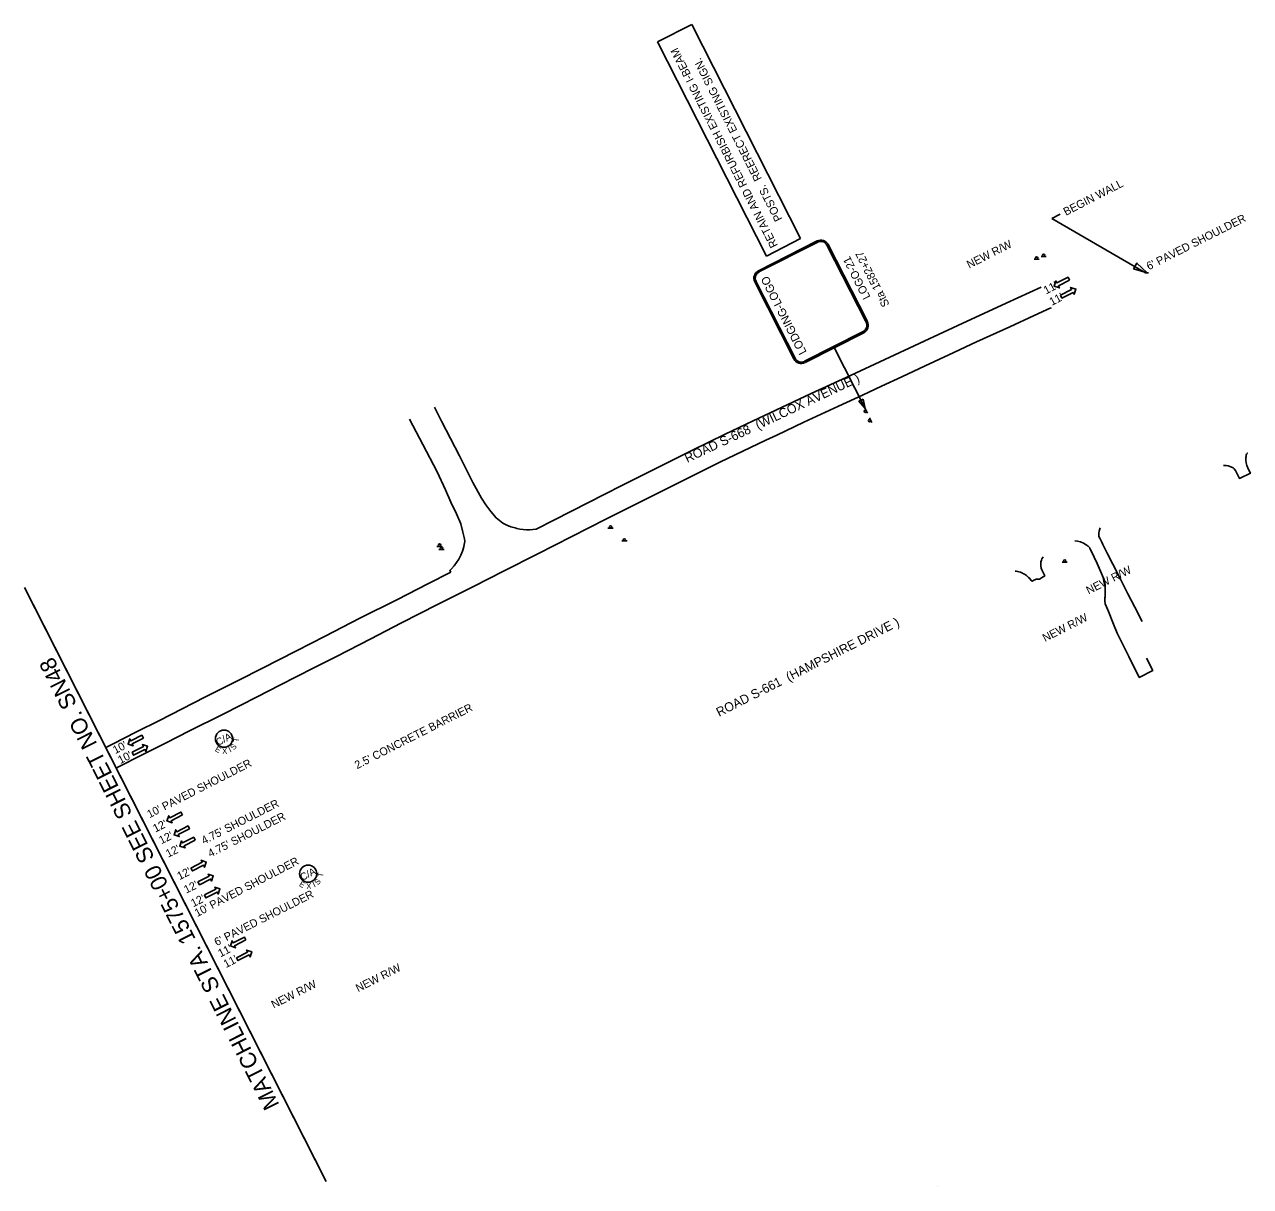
# Model space of a CAD drawing. Extents: x 1804682 to 1806347, y 1188229 to 1189604.
# Drawn here: x 1804682 to 1805754, y 1188229 to 1189245 of the extents above; entities that cross this region are included whole.
import ezdxf

# ---------------------------------------------------------------- set-up
doc = ezdxf.new("R2010")
doc.units = 0
for name, color, linetype in [('RD_EX_Road', 7, 'Continuous'), ('RD_PD_Final_LnLine', 7, 'Continuous'), ('RD_PD_Final_TX', 7, 'Continuous'), ('RD_PD_RW_TX', 7, 'Continuous'), ('RD_PD_WallFill', 7, 'Continuous'), ('RD_SHT_MatchLine', 7, 'Continuous'), ('RD_SHT_ShtClip', 7, 'Continuous'), ('RD_SHT_TX', 7, 'Continuous'), ('RD_Sketch8', 7, 'Continuous'), ('RD_TX_RoadID', 7, 'Continuous'), ('SN_P_Signs', 7, 'Continuous'), ('TERMINATOR', 7, 'Continuous')]:
    doc.layers.add(name, color=color, linetype=linetype)

# ---------------------------------------------------------------- blocks, each defined once
blk = doc.blocks.new('SARRW2')
at = {"layer": 'RD_PD_Final_LnLine'}
blk.add_lwpolyline([(-12, 1.2), (-12, -1.2), (-2.83, -1.2), (-2.83, -2.83), (0, 0), (-2.83, 2.83), (-2.83, 1.2)], close=True, dxfattribs=at)

msp = doc.modelspace()

# ---------------------------------------------------------------- linework, layer by layer
at = {"layer": 'RD_EX_Road'}
for points in [[(1805571.1, 1189015.4), (1805540.6, 1189001.4), (1805498.2, 1188981.7), (1805468.8, 1188968), (1805434.5, 1188952), (1805404.4, 1188938.1), (1805369.9, 1188922.2), (1805339.2, 1188907.8), (1805319.2, 1188898.3), (1805294.8, 1188886.7), (1805266.3, 1188872.8), (1805235.3, 1188857.4), (1805204.4, 1188841.9), (1805174.6, 1188826.7), (1805145.5, 1188811.9), (1805129.4, 1188803.7)], [(1804762.1, 1188594.8), (1804764.7, 1188596.2), (1804784.2, 1188606.1), (1804805.7, 1188616.9), (1804825.6, 1188627), (1804855.5, 1188642), (1804885.3, 1188657.2), (1804905.2, 1188667.2), (1804934.9, 1188682.4), (1804954.7, 1188692.5), (1804984.8, 1188707.9), (1805011, 1188721.4), (1805043.7, 1188738.1), (1805074.6, 1188753.7), (1805100.9, 1188766.9), (1805131, 1188782.2), (1805190.5, 1188812.4), (1805241, 1188837.9), (1805290.2, 1188862.3), (1805330.3, 1188881.5), (1805340, 1188886), (1805363.6, 1188897.2), (1805393.8, 1188911.2), (1805414.8, 1188920.9), (1805431.4, 1188928.6), (1805449.3, 1188937), (1805469.6, 1188946.4), (1805490.5, 1188956.1), (1805514.7, 1188967.5), (1805543.6, 1188980.7), (1805565.1, 1188990.5), (1805579.6, 1188997.1)], [(1805129.4, 1188803.7), (1805126.5, 1188803.3), (1805123.7, 1188803.1), (1805120.9, 1188803.2), (1805118, 1188803.4), (1805115.2, 1188803.8), (1805112.4, 1188804.4), (1805111.1, 1188804.8), (1805107.4, 1188805.9), (1805103.8, 1188807.3), (1805100.4, 1188809.1), (1805097.3, 1188811.2), (1805094.4, 1188813.6), (1805089.8, 1188819.2), (1805085.4, 1188825.1), (1805081.7, 1188830.7), (1805074.1, 1188844.5), (1805062.3, 1188867.7), (1805046.7, 1188898.2), (1805040.5, 1188910.4)], [(1805018.7, 1188899.9), (1805030.2, 1188877.8), (1805042.8, 1188853.9), (1805050.1, 1188838.2), (1805054.9, 1188827.4), (1805059.6, 1188817.1), (1805063.4, 1188808.3), (1805065.4, 1188801.2), (1805066.8, 1188795.4), (1805066.9, 1188792.8), (1805066.5, 1188790.2), (1805066.1, 1188788.4), (1805065, 1188784.6), (1805063.5, 1188780.9), (1805061.7, 1188777.4), (1805059.8, 1188774.5), (1805057.7, 1188771.7), (1805055.3, 1188769.1), (1805053.8, 1188767.7), (1805054.9, 1188766)], [(1805751.5, 1188870.2), (1805751.5, 1188870.2), (1805750.9, 1188869.3), (1805750.6, 1188868.3), (1805750.4, 1188867.2), (1805750.2, 1188866.5), (1805750.1, 1188864.1), (1805750.4, 1188861.8), (1805751.1, 1188859.5), (1805752.6, 1188855.9), (1805754.2, 1188852.6), (1805744.5, 1188848.1), (1805742.1, 1188853.4), (1805741.2, 1188855.1), (1805739.9, 1188856.6), (1805739, 1188857.2), (1805737, 1188858.3), (1805734.8, 1188859), (1805732.8, 1188859.4), (1805730.5, 1188859.5)], [(1805622.9, 1188804.8), (1805622.4, 1188804.1), (1805621.8, 1188802.1), (1805621.5, 1188800.1), (1805621.5, 1188799.2), (1805621.7, 1188797.6), (1805622.3, 1188796.1), (1805622.5, 1188795.8), (1805624.2, 1188792.3), (1805625.2, 1188790.3), (1805629.2, 1188782.2), (1805633.9, 1188773.1), (1805640.8, 1188759.4), (1805647, 1188747.2), (1805653, 1188735.5), (1805659.4, 1188723)], [(1805663.4, 1188691), (1805668.8, 1188680.3), (1805657, 1188674.1), (1805647.8, 1188692.4), (1805637.5, 1188712.8), (1805634.3, 1188720.6), (1805630, 1188731.6), (1805628.2, 1188735.9), (1805627.1, 1188738.4), (1805626.8, 1188741), (1805626.9, 1188743.7), (1805627, 1188744.7), (1805627.2, 1188750.9), (1805627, 1188754.9), (1805626.7, 1188757.6), (1805625.9, 1188760.3), (1805624.9, 1188762.8), (1805620, 1188773.7), (1805617.5, 1188779.1), (1805613.7, 1188787.1), (1805613.6, 1188787.4), (1805612.2, 1188788.8), (1805610.5, 1188790), (1805608.1, 1188791.4), (1805605.6, 1188792.5), (1805602.9, 1188793.2), (1805600.5, 1188793.5)], [(1805572.8, 1188779.4), (1805572.5, 1188779), (1805571.8, 1188777.8), (1805571.3, 1188776.5), (1805571, 1188775.1), (1805570.8, 1188773.7), (1805570.8, 1188773.5), (1805570.8, 1188771.6), (1805571.2, 1188769.7), (1805571.8, 1188768.2), (1805574.3, 1188762.8), (1805571.4, 1188761.2), (1805570.7, 1188760.7), (1805570.2, 1188760.4), (1805569.6, 1188760.1), (1805568.9, 1188760), (1805568.1, 1188760), (1805567.6, 1188760), (1805566.9, 1188759.9), (1805566.3, 1188759.7), (1805565.5, 1188759.4), (1805564.8, 1188759), (1805564, 1188758.5), (1805563.5, 1188758.2), (1805563, 1188758.2), (1805562.5, 1188758.7), (1805561.8, 1188759.6), (1805561.1, 1188760.6), (1805560.2, 1188761.5), (1805559.3, 1188762.4), (1805558.4, 1188763.1), (1805557.4, 1188763.8), (1805556.6, 1188764.3), (1805555.6, 1188764.8), (1805554.8, 1188765.2), (1805553.8, 1188765.7), (1805553, 1188766.1), (1805551.6, 1188766.5), (1805550.5, 1188766.8), (1805549.3, 1188767), (1805548.5, 1188767.1)], [(1805054.9, 1188766), (1805035.1, 1188756.3), (1805007.4, 1188742), (1804975.3, 1188725.8), (1804944.9, 1188710.1), (1804919.8, 1188697.4), (1804889.5, 1188681.8), (1804869.4, 1188671.8), (1804839.5, 1188656.7), (1804819.7, 1188646.6), (1804799.8, 1188636.5), (1804779.7, 1188626.4), (1804758.9, 1188615.8), (1804752.9, 1188612.8)]]:
    msp.add_lwpolyline(points, dxfattribs=at)
at = {"layer": 'RD_PD_Final_TX'}
for q in [(1805587.9, 1189079.1), (1805662.5, 1189027.9)]:
    msp.add_line((1805580.5, 1189075.3), q, dxfattribs=at)
at = {"layer": 'RD_PD_WallFill'}
msp.add_line((1805662.5, 1189027.9), (1805665, 1189027.7), dxfattribs=at)
at = {"layer": 'RD_SHT_MatchLine'}
msp.add_line((1804681.9, 1188752.7), (1804945.6, 1188233.5), dxfattribs=at)
at = {"layer": 'RD_SHT_ShtClip'}
msp.add_line((1804944.8, 1188235.2), (1804689.4, 1188737.9), dxfattribs=at)
at = {"layer": 'RD_SHT_TX'}
msp.add_line((1805579.6, 1188997.1), (1805579.8, 1188996.7), dxfattribs=at)
at = {"layer": 'RD_Sketch8'}
for centre in [(1804856.4, 1188620.5), (1804930, 1188502.5)]:
    msp.add_circle(centre, 7.5, dxfattribs=at)
at = {"layer": 'SN_P_Signs'}
for p, q in [((1805235.6, 1189229.7), (1805265.6, 1189244.9)), ((1805265.6, 1189244.9), (1805360.7, 1189057.7)), ((1805330.8, 1189042.4), (1805235.6, 1189229.7)), ((1805360.7, 1189057.7), (1805330.8, 1189042.4)), ((1805564.9, 1189039.7), (1805569.4, 1189039.7)), ((1805571.1, 1189042.2), (1805575.6, 1189042.2)), ((1805390.2, 1188962.5), (1805417.3, 1188909.2)), ((1805419.3, 1188905.2), (1805417.3, 1188909.2)), ((1805423, 1188897.1), (1805420.9, 1188901.1)), ((1805192.2, 1188804.6), (1805196.7, 1188804.6)), ((1805204.4, 1188793.4), (1805208.9, 1188793.4)), ((1805042.6, 1188788.7), (1805047.1, 1188788.7)), ((1805044.4, 1188786), (1805048.9, 1188786)), ((1805589.5, 1188774.9), (1805594, 1188774.9)), ((1805480.6, 1188229.1), (1805480.6, 1188229.1))]:
    msp.add_line(p, q, dxfattribs=at)
for points in [[(1805323.8, 1189029.7), (1805375.1, 1189055.8)], [(1805324.3, 1189028.6), (1805375.7, 1189054.7)], [(1805383.8, 1189052.1), (1805418, 1188984.7)], [(1805384.8, 1189052.6), (1805419.1, 1188985.2)], [(1805354.9, 1188952.6), (1805320.6, 1189020)], [(1805355.9, 1188953.1), (1805321.7, 1189020.5)], [(1805415.4, 1188976.6), (1805364, 1188950.5)], [(1805415.9, 1188975.5), (1805364.6, 1188949.4)]]:
    msp.add_lwpolyline(points, dxfattribs=at)
msp.add_lwpolyline([(1805415.4, 1188917.5), (1805417.3, 1188909.2), (1805411.7, 1188915.6)], close=True, dxfattribs=at)
for centre in [(1805567.1, 1189040.7), (1805573.3, 1189043.2), (1805417.4, 1188906.8), (1805421.1, 1188898.7), (1805194.5, 1188805.7), (1805206.6, 1188794.4), (1805044.9, 1188789.8), (1805046.7, 1188787), (1805591.8, 1188775.9)]:
    msp.add_circle(centre, 1, dxfattribs=at)
for centre, radius, start, end in [((1805378.4, 1189049.3), 7.2, 26.9317, 116.9317), ((1805378.4, 1189049.3), 6, 26.9317, 116.9317), ((1805327.1, 1189023.2), 7.2, 116.9317, 206.9317), ((1805327.1, 1189023.2), 6, 116.9317, 206.9317), ((1805412.6, 1188981.9), 6, 296.9317, 26.9317), ((1805412.6, 1188981.9), 7.2, 296.9317, 26.9317), ((1805361.3, 1188955.8), 7.2, 206.9317, 296.9317), ((1805361.3, 1188955.8), 6, 206.9317, 296.9317)]:
    msp.add_arc(centre, radius, start, end, dxfattribs=at)
at = {"layer": 'TERMINATOR'}
msp.add_lwpolyline([(1805651.9, 1189031.2), (1805663.8, 1189027.8), (1805654.9, 1189036.4)], close=True, dxfattribs=at)

# ---------------------------------------------------------------- block references
at = {"layer": 'RD_PD_Final_LnLine'}
for p, xscale, yscale, rotation in [((1805582.5, 1189016.2), 1.1999999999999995, 1.2000000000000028, -153.06833411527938), ((1805601.5, 1189013.6), 1.1999999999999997, 1.2000000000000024, 26.931665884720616), ((1804772.4, 1188615.8), 1.1999999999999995, 1.2000000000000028, -153.06833411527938), ((1804789.5, 1188613.9), 1.1999999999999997, 1.2000000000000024, 26.931665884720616), ((1804806.5, 1188548.6), 1.1999999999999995, 1.2000000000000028, -153.06833411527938), ((1804812.7, 1188536.4), 1.1999999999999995, 1.2000000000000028, -153.06833411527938), ((1804817.7, 1188526.6), 1.1999999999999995, 1.2000000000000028, -153.06833411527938), ((1804840.9, 1188512.7), 1.1999999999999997, 1.2000000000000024, 26.931665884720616), ((1804847, 1188500.6), 1.1999999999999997, 1.2000000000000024, 26.931665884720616), ((1804852.8, 1188489.2), 1.1999999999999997, 1.2000000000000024, 26.931665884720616), ((1804862, 1188439.3), 1.1999999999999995, 1.2000000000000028, -153.06833411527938), ((1804880.7, 1188434.3), 1.1999999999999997, 1.2000000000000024, 26.931665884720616)]:
    msp.add_blockref('SARRW2', p, dxfattribs=dict(at, xscale=xscale, yscale=yscale, rotation=rotation))

# ---------------------------------------------------------------- texts
at = {"layer": 'RD_PD_Final_TX'}
for s, rotation, p in [('BEGIN WALL', 27.1817, (1805592.8, 1189077.6)), ("6' PAVED SHOULDER", 26.8178, (1805665.4, 1189030)), ("11'", 27.1817, (1805575.4, 1189008.9)), ("11'", 27.1817, (1805580.5, 1188998.9)), ("2.5' CONCRETE BARRIER", 26.9334, (1804972.8, 1188593.8)), ("10'", 27.1817, (1804761.3, 1188607)), ("10'", 27.1817, (1804765.7, 1188598.3)), ("10' PAVED SHOULDER", 27.0678, (1804791.2, 1188550.9)), ("4.75' SHOULDER", 26.9317, (1804838.7, 1188527.9)), ("4.75' SHOULDER", 26.9317, (1804844.4, 1188516.6)), ("12'", 26.3048, (1804796.3, 1188538.4)), ("12'", 26.3048, (1804801.5, 1188528.1)), ("12'", 26.3048, (1804807.5, 1188516.4)), ("10' PAVED SHOULDER", 27.5678, (1804832.9, 1188464.5)), ("12'", 26.3048, (1804817.4, 1188496.8)), ("12'", 26.3048, (1804823.4, 1188485)), ("12'", 26.3048, (1804829.5, 1188473.1)), ("6' PAVED SHOULDER", 26.8178, (1804850, 1188439.1)), ("11'", 27.1817, (1804853.3, 1188429.3)), ("11'", 27.1817, (1804858.1, 1188419.9))]:
    msp.add_text(s, height=7, rotation=rotation, dxfattribs=at).set_placement(p)
at = {"layer": 'RD_PD_RW_TX'}
for p in [(1805508.2, 1189031.4), (1805612.7, 1188746.6), (1805574.5, 1188705), (1804973.7, 1188398.8), (1804899.9, 1188384.5)]:
    msp.add_text('NEW R/W', height=7, rotation=26.7549, dxfattribs=at).set_placement(p)
at = {"layer": 'RD_SHT_TX'}
msp.add_text('MATCHLINE STA. 1575+00 SEE SHEET NO. SN48', height=14.173, rotation=116.813, dxfattribs=at).set_placement((1804905.1, 1188300.5))
at = {"layer": 'RD_Sketch8'}
for s, height, rotation, p in [('C/A', 6.25, 26.9317, (1804851.3, 1188614.2)), ('T', 5, 85.1168, (1804869.4, 1188617.3)), ('E', 5, 330.1429, (1804848, 1188610)), ('X', 5, 2.5723, (1804854.8, 1188607.1)), ('I', 5, 26.7323, (1804861.8, 1188608.4)), ('S', 5, 48.7241, (1804865, 1188610.2)), ('C/A', 6.25, 26.9317, (1804924.9, 1188496.2)), ('T', 5, 85.1168, (1804943.1, 1188499.3)), ('E', 5, 330.1429, (1804921.6, 1188492)), ('X', 5, 2.5723, (1804928.4, 1188489.1)), ('I', 5, 26.7323, (1804935.4, 1188490.4)), ('S', 5, 48.7241, (1804938.6, 1188492.2))]:
    msp.add_text(s, height=height, rotation=rotation, dxfattribs=at).set_placement(p)
at = {"layer": 'RD_TX_RoadID'}
for s, rotation, p in [('ROAD S-668  (WILCOX AVENUE )', 25.2067, (1805261.6, 1188861.6)), ('ROAD S-661  (HAMPSHIRE DRIVE )', 26.8493, (1805289.4, 1188639.5))]:
    msp.add_text(s, height=8, rotation=rotation, dxfattribs=at).set_placement(p)
at = {"layer": 'SN_P_Signs'}
for s, height, p in [('RETAIN AND REFURBISH EXISTING I-BEAM', 7, (1805341, 1189051.8)), ('POSTS.  REERECT EXISTING SIGN.', 7, (1805344.9, 1189074.9)), ('LOGO-21', 7, (1805422, 1189006.7)), ('Sta 1582+27', 7, (1805438.7, 1189000.1)), ('LODGING-LOGO', 7.2, (1805366.2, 1188958.5))]:
    msp.add_text(s, height=height, rotation=116.9317, dxfattribs=at).set_placement(p)

doc.saveas('drawing.dxf')
